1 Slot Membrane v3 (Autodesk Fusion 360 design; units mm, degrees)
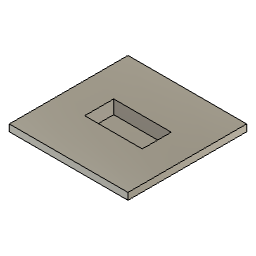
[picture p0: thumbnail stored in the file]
sketch "Sketch1" plane through (0, 0, 0) normal (0, 0, 1) x axis (1, 0, 0)
  line L1 (5.4, 0) -> (0, 0)
  line L2 (5.4, 5.4) -> (5.4, 0)
  line L3 (0, 5.4) -> (5.4, 5.4)
  line L4 (0, 0) -> (0, 5.4)
  point P1 (0, 0)
  point P2 (0, 0)
  horizontal L1
  vertical L2
  horizontal L3
  vertical L4
  coincident P1 P2
  dimension "d1" distance L2 L4 = 5.4
  dimension "d2" distance L1 L3 = 5.4
extrude "Extrude1" new body sketch "Sketch1" along normal blind 0.31
sketch "Sketch2" plane through (0, 0, 0.31) normal (0, 0, 1) x axis (-1, 0, 0)
  line L1 (-1.7, -2.35) -> (-3.7, -2.35)
  line L2 (-1.7, -3.05) -> (-1.7, -2.35)
  line L3 (-3.7, -3.05) -> (-1.7, -3.05)
  line L4 (-3.7, -2.35) -> (-3.7, -3.05)
  line L5 (0, 0) -> (0, -5.4)
  line L6 (-5.4, 0) -> (0, 0)
  line L7 (-5.4, -5.4) -> (-5.4, 0)
  line L8 (0, -5.4) -> (-5.4, -5.4)
  point P1 (0, 0)
  horizontal L1
  vertical L2
  horizontal L3
  vertical L4
  dimension "d8" distance L1 L3 = 0.7
  dimension "d9" distance L2 L4 = 2
  dimension "d10" distance P1 L2 = 1.7
  dimension "d11" distance P1 L1 = 2.35
extrude "Extrude2" cut sketch "Sketch2" profile of L1 L2 L3 L4 against normal blind 3
chamfer "Chamfer2" distance 0.31 Rotate Angle 45
component_from_bodies "Body->Comp"
sketch "Sketch3" plane through (0, 0, 0) normal (0, 0, -1) x axis (1, 0, 0)
  line L1 (1.7, -2.35) -> (1.7, -3.05)
  line L2 (3.7, -2.35) -> (1.7, -2.35)
  line L3 (3.7, -3.05) -> (3.7, -2.35)
  line L4 (1.7, -3.05) -> (3.7, -3.05)
  line L5 (0, -5.4) -> (0, 0)
  line L6 (5.4, -5.4) -> (0, -5.4)
  line L7 (5.4, 0) -> (5.4, -5.4)
  line L8 (0, 0) -> (5.4, 0)
  line L9 (0, -5.4) -> (5.4, -5.4)
  line L10 (0, 0) -> (0, -5.4)
  line L11 (5.4, 0) -> (0, 0)
  line L12 (5.4, -5.4) -> (5.4, 0)
  point P6 (0, 0)
  point P12 (0, 0)
  point P8 (5.4, -5.4)
  point P10 (5.4, -5.4)
  horizontal L9
  vertical L10
  horizontal L11
  vertical L12
  coincident P6 P12
  coincident P8 P10
place_component sketch "Sketch3"
extrude "Extrude1" new body sketch "Sketch3" along normal blind 0.0001 (= "100 nm")
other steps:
base_feature "Base Feature"
create_component "CreateComponent1"
remove_body "RemoveBody1"
create_component "CreateComponent2" sketch "Sketch3"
